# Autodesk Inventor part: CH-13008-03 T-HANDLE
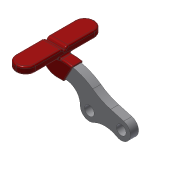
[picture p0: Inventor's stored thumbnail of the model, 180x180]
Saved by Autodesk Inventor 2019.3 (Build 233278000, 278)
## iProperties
Created: 2012-09
Part Number: CH-13008-03 T-HANDLE
Material: Ogólny
Document SubType Name: Modeling
Designer: CADENGINEERING4
Density: 1 g/cm^3
Appearance: Domyślna
Author: CADENGINEERING4
Revision Number: ÈÎºÎ
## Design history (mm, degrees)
feature "Ô²½Ç10"
node "Bryła1"
